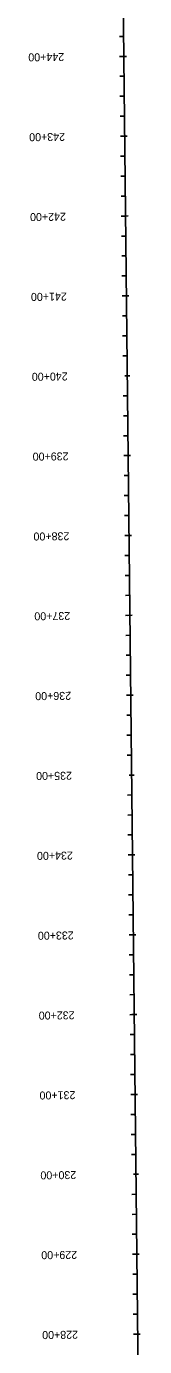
# Model space of a CAD drawing. Extents: x 23417911 to 23421158, y 6737892 to 6791804.
# Drawn here: x 23418150 to 23418293, y 6749259 to 6750912 of the extents above; entities that cross this region are included whole.
import ezdxf

# ---------------------------------------------------------------- set-up
doc = ezdxf.new("R2010")
doc.units = 0
for name, color, linetype in [('Alignment', 7, 'Continuous'), ('TextAlignmentLrg', 7, 'Continuous'), ('TextAlignmentSml', 7, 'Continuous')]:
    doc.layers.add(name, color=color, linetype=linetype)

msp = doc.modelspace()

# ---------------------------------------------------------------- linework, layer by layer
at = {"layer": 'Alignment'}
msp.add_line((23418292.6, 6748745.2), (23418260.7, 6751686.6), dxfattribs=at)
msp.add_line((23418292.6, 6748745.2), (23418260.7, 6751686.6), dxfattribs=at)
at = {"layer": 'TextAlignmentLrg'}
for p, q in [((23418269.5, 6750874.6), (23418264, 6750874.6)), ((23418270.6, 6750774.6), (23418265.1, 6750774.6)), ((23418271.7, 6750674.6), (23418266.2, 6750674.6)), ((23418272.7, 6750574.6), (23418267.3, 6750574.6)), ((23418270.8, 6750474.6), (23418276.9, 6750474.7)), ((23418274.9, 6750374.6), (23418269.5, 6750374.6)), ((23418276, 6750274.7), (23418270.5, 6750274.6)), ((23418277.1, 6750174.7), (23418271.6, 6750174.6)), ((23418278.2, 6750074.7), (23418272.7, 6750074.6)), ((23418276.2, 6749974.6), (23418282.3, 6749974.7)), ((23418280.3, 6749874.7), (23418274.9, 6749874.6)), ((23418281.4, 6749774.7), (23418276, 6749774.6)), ((23418282.5, 6749674.7), (23418277, 6749674.6)), ((23418283.6, 6749574.7), (23418278.1, 6749574.6)), ((23418281.6, 6749474.7), (23418287.7, 6749474.7)), ((23418285.8, 6749374.7), (23418280.3, 6749374.6)), ((23418286.8, 6749274.7), (23418281.4, 6749274.7))]:
    msp.add_line(p, q, dxfattribs=at)
at = {"layer": 'TextAlignmentSml'}
for p, q in [((23418269.2, 6750899.6), (23418263.8, 6750899.6)), ((23418266.4, 6750874.6), (23418272.6, 6750874.6)), ((23418269.8, 6750849.6), (23418264.3, 6750849.6)), ((23418270, 6750824.6), (23418264.6, 6750824.6)), ((23418270.3, 6750799.6), (23418264.8, 6750799.6)), ((23418267.5, 6750774.6), (23418273.6, 6750774.7)), ((23418270.9, 6750749.6), (23418265.4, 6750749.6)), ((23418271.1, 6750724.6), (23418265.7, 6750724.6)), ((23418271.4, 6750699.6), (23418265.9, 6750699.6)), ((23418268.6, 6750674.6), (23418274.7, 6750674.7)), ((23418271.9, 6750649.6), (23418266.5, 6750649.6)), ((23418272.2, 6750624.6), (23418266.7, 6750624.6)), ((23418272.5, 6750599.6), (23418267, 6750599.6)), ((23418269.7, 6750574.6), (23418275.8, 6750574.7)), ((23418273, 6750549.6), (23418267.6, 6750549.6)), ((23418273.3, 6750524.6), (23418267.8, 6750524.6)), ((23418273.6, 6750499.6), (23418268.1, 6750499.6)), ((23418270.8, 6750474.6), (23418276.9, 6750474.7)), ((23418274.1, 6750449.6), (23418268.6, 6750449.6)), ((23418274.4, 6750424.6), (23418268.9, 6750424.6)), ((23418274.6, 6750399.6), (23418269.2, 6750399.6)), ((23418271.9, 6750374.6), (23418278, 6750374.7)), ((23418275.2, 6750349.6), (23418269.7, 6750349.6)), ((23418275.5, 6750324.6), (23418270, 6750324.6)), ((23418275.7, 6750299.6), (23418270.3, 6750299.6)), ((23418272.9, 6750274.6), (23418279.1, 6750274.7)), ((23418276.3, 6750249.7), (23418270.8, 6750249.6)), ((23418276.5, 6750224.7), (23418271.1, 6750224.6)), ((23418276.8, 6750199.7), (23418271.4, 6750199.6)), ((23418274, 6750174.6), (23418280.1, 6750174.7)), ((23418277.4, 6750149.7), (23418271.9, 6750149.6)), ((23418277.6, 6750124.7), (23418272.2, 6750124.6)), ((23418277.9, 6750099.7), (23418272.4, 6750099.6)), ((23418275.1, 6750074.6), (23418281.2, 6750074.7)), ((23418278.4, 6750049.7), (23418273, 6750049.6)), ((23418278.7, 6750024.7), (23418273.2, 6750024.6)), ((23418279, 6749999.7), (23418273.5, 6749999.6)), ((23418276.2, 6749974.6), (23418282.3, 6749974.7)), ((23418279.5, 6749949.7), (23418274.1, 6749949.6)), ((23418279.8, 6749924.7), (23418274.3, 6749924.6)), ((23418280.1, 6749899.7), (23418274.6, 6749899.6)), ((23418277.3, 6749874.6), (23418283.4, 6749874.7)), ((23418280.6, 6749849.7), (23418275.1, 6749849.6)), ((23418280.9, 6749824.7), (23418275.4, 6749824.6)), ((23418281.1, 6749799.7), (23418275.7, 6749799.6)), ((23418278.4, 6749774.6), (23418284.5, 6749774.7)), ((23418281.7, 6749749.7), (23418276.2, 6749749.6)), ((23418282, 6749724.7), (23418276.5, 6749724.6)), ((23418282.2, 6749699.7), (23418276.8, 6749699.6)), ((23418279.4, 6749674.7), (23418285.6, 6749674.7)), ((23418282.8, 6749649.7), (23418277.3, 6749649.6)), ((23418283, 6749624.7), (23418277.6, 6749624.6)), ((23418283.3, 6749599.7), (23418277.9, 6749599.6)), ((23418280.5, 6749574.7), (23418286.6, 6749574.7)), ((23418283.9, 6749549.7), (23418278.4, 6749549.6)), ((23418284.1, 6749524.7), (23418278.7, 6749524.6)), ((23418284.4, 6749499.7), (23418278.9, 6749499.6)), ((23418281.6, 6749474.7), (23418287.7, 6749474.7)), ((23418284.9, 6749449.7), (23418279.5, 6749449.6)), ((23418285.2, 6749424.7), (23418279.8, 6749424.6)), ((23418285.5, 6749399.7), (23418280, 6749399.6)), ((23418282.7, 6749374.7), (23418288.8, 6749374.7)), ((23418286, 6749349.7), (23418280.6, 6749349.6)), ((23418286.3, 6749324.7), (23418280.8, 6749324.6)), ((23418286.6, 6749299.7), (23418281.1, 6749299.6)), ((23418283.8, 6749274.7), (23418289.9, 6749274.7))]:
    msp.add_line(p, q, dxfattribs=at)

# ---------------------------------------------------------------- texts
at = {"layer": 'TextAlignmentLrg'}
for s, p in [('240+00', (23418198.8, 6750478.8)), ('235+00', (23418204.2, 6749978.9)), ('230+00', (23418209.6, 6749478.9))]:
    msp.add_text(s, height=10.02, rotation=180.6211, dxfattribs=at).set_placement(p)
at = {"layer": 'TextAlignmentSml'}
for s, p in [('244+00', (23418194.4, 6750878.8)), ('243+00', (23418195.5, 6750778.8)), ('242+00', (23418196.6, 6750678.8)), ('241+00', (23418197.7, 6750578.8)), ('240+00', (23418198.8, 6750478.8)), ('239+00', (23418199.9, 6750378.8)), ('238+00', (23418200.9, 6750278.8)), ('237+00', (23418202, 6750178.9)), ('236+00', (23418203.1, 6750078.9)), ('235+00', (23418204.2, 6749978.9)), ('234+00', (23418205.3, 6749878.9)), ('233+00', (23418206.4, 6749778.9)), ('232+00', (23418207.5, 6749678.9)), ('231+00', (23418208.5, 6749578.9)), ('230+00', (23418209.6, 6749478.9)), ('229+00', (23418210.7, 6749378.9)), ('228+00', (23418211.8, 6749278.9))]:
    msp.add_text(s, height=10.02, rotation=180.6211, dxfattribs=at).set_placement(p)

doc.saveas('drawing.dxf')
